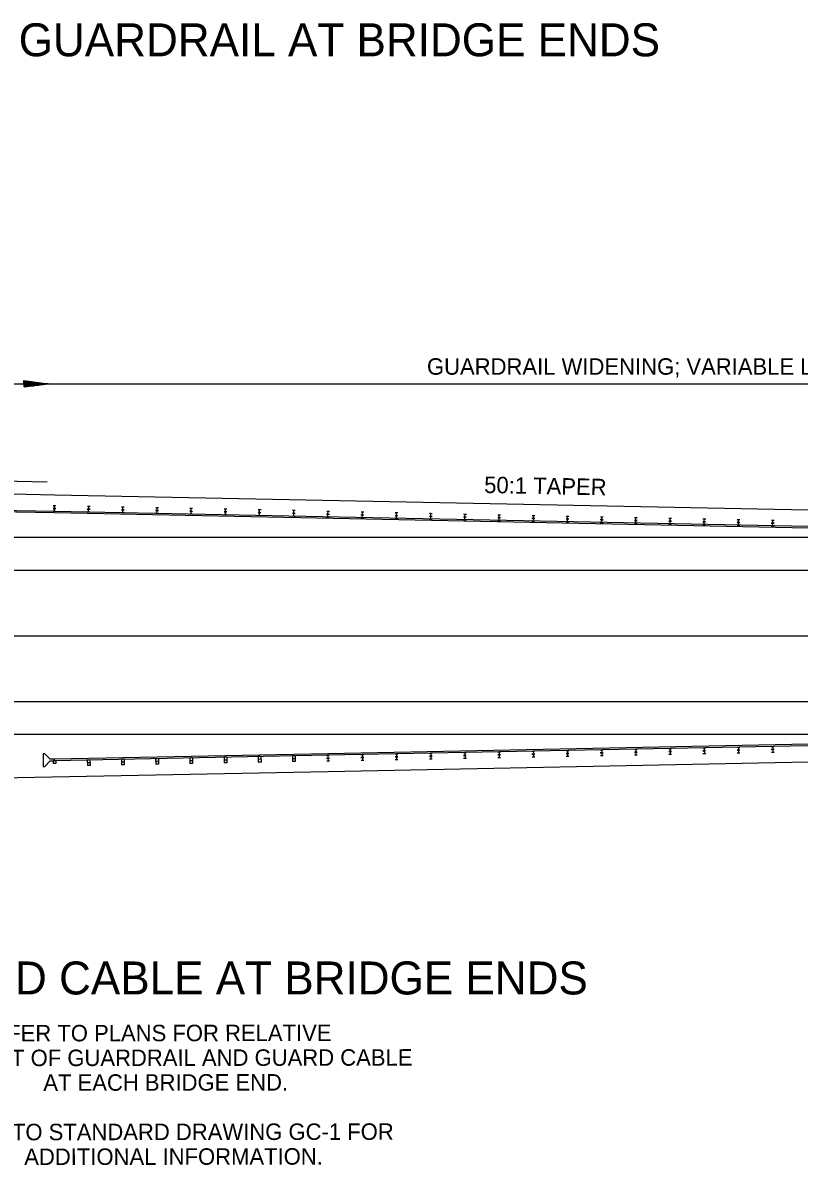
# Model space of a CAD drawing. Extents: x -2842 to 2681, y -2139 to 474.
# Drawn here: x -2274.9 to -1992.1, y -1829.5 to -1413.5 of the extents above; entities that cross this region are included whole.
import ezdxf

# ---------------------------------------------------------------- set-up
doc = ezdxf.new("R2010")
doc.units = 0
for name, color, linetype in [('Default', 7, 'Continuous'), ('R_Border', 7, 'Continuous'), ('R_Border Notes', 7, 'Continuous'), ('R_Grid', 7, 'Continuous')]:
    doc.layers.add(name, color=color, linetype=linetype)

msp = doc.modelspace()

# ---------------------------------------------------------------- linework, layer by layer
at = {"layer": 'Default'}
for p, q in [((-2263.31, -1585.48), (-2381.26, -1583.13)), ((-1814.89, -1594.45), (-2263.31, -1585.48)), ((-2263.45, -1592), (-2359.64, -1590.08)), ((-2263.43, -1591.46), (-2359.58, -1589.54)), ((-2263.43, -1591.46), (-2263.93, -1591.46)), ((-2263.41, -1590.39), (-2263.91, -1590.37)), ((-2263.41, -1590.47), (-2263.91, -1590.47)), ((-2263.39, -1589.39), (-2263.89, -1589.37)), ((-1815.02, -1600.97), (-2263.45, -1592)), ((-2263.43, -1591.46), (-2263.41, -1590.47)), ((-1815, -1600.43), (-2263.43, -1591.46)), ((-2262.93, -1591.48), (-2263.43, -1591.46)), ((-2263.41, -1590.39), (-2263.39, -1589.39)), ((-2262.91, -1590.41), (-2263.41, -1590.39)), ((-2262.91, -1590.49), (-2263.41, -1590.47)), ((-2262.89, -1589.41), (-2263.39, -1589.39)), ((-2250.97, -1591.72), (-2251.49, -1591.7)), ((-2250.95, -1590.65), (-2251.45, -1590.63)), ((-2250.97, -1590.72), (-2251.45, -1590.7)), ((-2250.93, -1589.65), (-2251.43, -1589.63)), ((-2250.97, -1591.72), (-2250.97, -1590.72)), ((-2250.46, -1590.72), (-2250.97, -1590.72)), ((-2250.5, -1591.72), (-2250.97, -1591.72)), ((-2250.95, -1590.65), (-2250.93, -1589.65)), ((-2250.46, -1590.65), (-2250.95, -1590.65)), ((-2250.44, -1589.65), (-2250.93, -1589.65)), ((-2238.54, -1591.96), (-2239.04, -1591.96)), ((-2238.5, -1590.88), (-2239.02, -1590.88)), ((-2238.52, -1590.96), (-2239.02, -1590.96)), ((-2238.5, -1589.89), (-2238.98, -1589.89)), ((-2238.54, -1591.96), (-2238.52, -1590.96)), ((-2238.04, -1591.98), (-2238.54, -1591.96)), ((-2238.02, -1590.98), (-2238.52, -1590.96)), ((-2238.5, -1590.88), (-2238.5, -1589.89)), ((-2237.98, -1589.89), (-2238.5, -1589.89)), ((-2238.02, -1590.88), (-2238.5, -1590.88)), ((-2226.08, -1592.22), (-2226.58, -1592.2)), ((-2226.06, -1591.12), (-2226.56, -1591.12)), ((-2226.06, -1591.22), (-2226.56, -1591.2)), ((-2226.04, -1590.13), (-2226.54, -1590.13)), ((-2226.08, -1592.22), (-2226.06, -1591.22)), ((-2225.58, -1592.22), (-2226.08, -1592.22)), ((-2226.06, -1591.12), (-2226.04, -1590.13)), ((-2225.56, -1591.14), (-2226.06, -1591.12)), ((-2225.56, -1591.22), (-2226.06, -1591.22)), ((-2225.54, -1590.15), (-2226.04, -1590.13)), ((-2213.62, -1592.46), (-2214.12, -1592.46)), ((-2213.6, -1591.38), (-2214.1, -1591.38)), ((-2213.6, -1591.46), (-2214.1, -1591.46)), ((-2213.58, -1590.39), (-2214.08, -1590.39)), ((-2213.62, -1592.46), (-2213.6, -1591.46)), ((-2213.12, -1592.48), (-2213.62, -1592.46)), ((-2213.6, -1591.38), (-2213.58, -1590.39)), ((-2213.1, -1591.4), (-2213.6, -1591.38)), ((-2213.1, -1591.48), (-2213.6, -1591.46)), ((-2213.08, -1590.41), (-2213.58, -1590.39)), ((-2201.17, -1592.72), (-2201.66, -1592.7)), ((-2201.15, -1591.64), (-2201.64, -1591.62)), ((-2201.15, -1591.72), (-2201.64, -1591.7)), ((-2201.13, -1590.65), (-2201.62, -1590.63)), ((-2201.17, -1592.72), (-2201.15, -1591.72)), ((-2200.67, -1592.72), (-2201.17, -1592.72)), ((-2201.15, -1591.64), (-2201.13, -1590.65)), ((-2200.65, -1591.64), (-2201.15, -1591.64)), ((-2200.65, -1591.72), (-2201.15, -1591.72)), ((-2200.63, -1590.65), (-2201.13, -1590.65)), ((-2188.71, -1592.96), (-2189.21, -1592.96)), ((-2188.69, -1591.88), (-2189.19, -1591.88)), ((-2188.69, -1591.96), (-2189.19, -1591.96)), ((-2188.67, -1590.88), (-2189.17, -1590.88)), ((-2188.71, -1592.96), (-2188.69, -1591.96)), ((-2188.21, -1592.98), (-2188.71, -1592.96)), ((-2188.69, -1591.88), (-2188.67, -1590.88)), ((-2188.19, -1591.9), (-2188.69, -1591.88)), ((-2188.19, -1591.98), (-2188.69, -1591.96)), ((-2188.17, -1590.9), (-2188.67, -1590.88)), ((-2176.25, -1593.22), (-2176.75, -1593.2)), ((-2176.23, -1592.14), (-2176.73, -1592.12)), ((-2176.23, -1592.22), (-2176.73, -1592.2)), ((-2176.21, -1591.14), (-2176.71, -1591.12)), ((-2176.25, -1593.22), (-2176.23, -1592.22)), ((-2175.75, -1593.22), (-2176.25, -1593.22)), ((-2176.23, -1592.14), (-2176.21, -1591.14)), ((-2175.73, -1592.14), (-2176.23, -1592.14)), ((-2175.73, -1592.22), (-2176.23, -1592.22)), ((-2175.71, -1591.14), (-2176.21, -1591.14)), ((-2164.27, -1592.36), (-2163.78, -1592.38)), ((-2164.27, -1592.44), (-2163.78, -1592.46)), ((-2164.25, -1591.36), (-2163.76, -1591.38)), ((-2163.8, -1593.46), (-2163.78, -1592.46)), ((-2163.78, -1592.38), (-2163.76, -1591.38)), ((-2163.78, -1592.38), (-2163.28, -1592.38)), ((-2163.78, -1592.46), (-2163.28, -1592.46)), ((-2163.76, -1591.38), (-2163.26, -1591.38)), ((-2151.76, -1592.62), (-2151.26, -1592.62)), ((-2151.76, -1592.7), (-2151.26, -1592.7)), ((-2151.74, -1591.62), (-2151.24, -1591.62)), ((-2151.28, -1593.69), (-2151.26, -1592.7)), ((-2151.26, -1592.62), (-2151.24, -1591.62)), ((-2151.26, -1592.62), (-2150.76, -1592.64)), ((-2151.26, -1592.7), (-2150.76, -1592.72)), ((-2151.24, -1591.62), (-2150.74, -1591.64)), ((-2139.3, -1592.86), (-2138.8, -1592.88)), ((-2139.3, -1592.94), (-2138.8, -1592.96)), ((-2139.28, -1591.86), (-2138.78, -1591.88)), ((-2138.82, -1593.95), (-2138.8, -1592.96)), ((-2138.8, -1592.88), (-2138.78, -1591.88)), ((-2138.8, -1592.88), (-2138.3, -1592.88)), ((-2138.8, -1592.96), (-2138.3, -1592.96)), ((-2138.78, -1591.88), (-2138.28, -1591.88)), ((-2126.84, -1593.12), (-2126.35, -1593.12)), ((-2126.84, -1593.2), (-2126.35, -1593.2)), ((-2126.82, -1592.12), (-2126.33, -1592.12)), ((-2126.37, -1594.19), (-2126.35, -1593.2)), ((-2126.35, -1593.12), (-2126.33, -1592.12)), ((-2126.35, -1593.12), (-2125.85, -1593.14)), ((-2126.35, -1593.2), (-2125.85, -1593.22)), ((-2126.33, -1592.12), (-2125.83, -1592.14)), ((-2114.37, -1592.36), (-2113.87, -1592.38)), ((-2113.89, -1593.38), (-2113.87, -1592.38)), ((-2113.87, -1592.38), (-2113.37, -1592.38)), ((-2101.91, -1592.62), (-2101.41, -1592.62)), ((-2101.43, -1593.61), (-2101.41, -1592.62)), ((-2101.41, -1592.62), (-2100.91, -1592.64)), ((-2089.45, -1592.86), (-2088.96, -1592.88)), ((-2088.98, -1593.87), (-2088.96, -1592.88)), ((-2088.96, -1592.88), (-2088.46, -1592.88)), ((-2077, -1593.12), (-2076.5, -1593.12)), ((-2076.52, -1594.11), (-2076.5, -1593.12)), ((-2076.5, -1593.12), (-2076, -1593.14)), ((-2164.29, -1593.44), (-2163.8, -1593.46)), ((-2163.8, -1593.46), (-2163.3, -1593.46)), ((-2151.78, -1593.69), (-2151.28, -1593.69)), ((-2151.28, -1593.69), (-2150.78, -1593.71)), ((-2139.32, -1593.93), (-2138.82, -1593.95)), ((-2138.82, -1593.95), (-2138.32, -1593.95)), ((-2126.86, -1594.19), (-2126.37, -1594.19)), ((-2126.37, -1594.19), (-2125.87, -1594.21)), ((-2114.41, -1594.43), (-2113.91, -1594.45)), ((-2114.39, -1593.36), (-2113.89, -1593.38)), ((-2114.39, -1593.44), (-2113.89, -1593.46)), ((-2113.91, -1594.45), (-2113.89, -1593.46)), ((-2113.91, -1594.45), (-2113.41, -1594.45)), ((-2113.89, -1593.38), (-2113.39, -1593.38)), ((-2113.89, -1593.46), (-2113.39, -1593.46)), ((-2101.95, -1594.69), (-2101.45, -1594.69)), ((-2101.93, -1593.61), (-2101.43, -1593.61)), ((-2101.93, -1593.69), (-2101.43, -1593.69)), ((-2101.45, -1594.69), (-2101.43, -1593.69)), ((-2101.45, -1594.69), (-2100.95, -1594.71)), ((-2101.43, -1593.61), (-2100.93, -1593.63)), ((-2101.43, -1593.69), (-2100.93, -1593.71)), ((-2089.49, -1594.93), (-2089, -1594.95)), ((-2089.47, -1593.85), (-2088.98, -1593.87)), ((-2089.47, -1593.93), (-2088.98, -1593.95)), ((-2089, -1594.95), (-2088.98, -1593.95)), ((-2089, -1594.95), (-2088.5, -1594.95)), ((-2088.98, -1593.87), (-2088.48, -1593.87)), ((-2088.98, -1593.95), (-2088.48, -1593.95)), ((-2077.06, -1595.19), (-2076.54, -1595.19)), ((-2077.02, -1594.11), (-2076.52, -1594.11)), ((-2077.02, -1594.19), (-2076.54, -1594.19)), ((-2076.54, -1595.19), (-2076.54, -1594.19)), ((-2076.54, -1594.19), (-2076.02, -1594.21)), ((-2076.54, -1595.19), (-2076.06, -1595.21)), ((-2076.52, -1594.11), (-2076.02, -1594.13)), ((-2064.6, -1595.43), (-2064.1, -1595.45)), ((-2064.58, -1594.35), (-2064.06, -1594.37)), ((-2064.58, -1594.43), (-2064.08, -1594.45)), ((-2064.54, -1593.36), (-2064.06, -1593.38)), ((-2064.1, -1595.45), (-2064.08, -1594.45)), ((-2064.1, -1595.45), (-2063.6, -1595.45)), ((-2064.08, -1594.45), (-2063.58, -1594.45)), ((-2064.06, -1594.37), (-2064.06, -1593.38)), ((-2064.06, -1593.38), (-2063.54, -1593.38)), ((-2064.06, -1594.37), (-2063.58, -1594.37)), ((-2052.14, -1595.69), (-2051.64, -1595.69)), ((-2052.12, -1594.61), (-2051.62, -1594.61)), ((-2052.12, -1594.69), (-2051.62, -1594.69)), ((-2052.1, -1593.61), (-2051.6, -1593.61)), ((-2051.64, -1595.69), (-2051.62, -1594.69)), ((-2051.64, -1595.69), (-2051.15, -1595.71)), ((-2051.62, -1594.61), (-2051.6, -1593.61)), ((-2051.62, -1594.61), (-2051.13, -1594.63)), ((-2051.62, -1594.69), (-2051.13, -1594.71)), ((-2051.6, -1593.61), (-2051.11, -1593.63)), ((-2039.69, -1595.93), (-2039.19, -1595.95)), ((-2039.67, -1594.85), (-2039.17, -1594.87)), ((-2039.67, -1594.93), (-2039.17, -1594.95)), ((-2039.65, -1593.85), (-2039.15, -1593.87)), ((-2039.19, -1595.95), (-2039.17, -1594.95)), ((-2039.19, -1595.95), (-2038.69, -1595.95)), ((-2039.17, -1594.87), (-2039.15, -1593.87)), ((-2039.17, -1594.87), (-2038.67, -1594.87)), ((-2039.17, -1594.95), (-2038.67, -1594.95)), ((-2039.15, -1593.87), (-2038.65, -1593.87)), ((-2027.23, -1596.19), (-2026.73, -1596.19)), ((-2027.21, -1595.11), (-2026.71, -1595.11)), ((-2027.21, -1595.19), (-2026.71, -1595.19)), ((-2027.19, -1594.11), (-2026.69, -1594.11)), ((-2026.73, -1596.19), (-2026.71, -1595.19)), ((-2026.73, -1596.19), (-2026.23, -1596.21)), ((-2026.71, -1595.11), (-2026.69, -1594.11)), ((-2026.71, -1595.11), (-2026.21, -1595.13)), ((-2026.71, -1595.19), (-2026.21, -1595.21)), ((-2026.69, -1594.11), (-2026.19, -1594.13)), ((-2014.77, -1596.43), (-2014.27, -1596.44)), ((-2014.75, -1595.35), (-2014.25, -1595.37)), ((-2014.75, -1595.43), (-2014.25, -1595.45)), ((-2014.73, -1594.35), (-2014.23, -1594.37)), ((-2014.27, -1596.44), (-2014.25, -1595.45)), ((-2014.27, -1596.44), (-2013.78, -1596.44)), ((-2014.25, -1595.37), (-2014.23, -1594.37)), ((-2014.25, -1595.37), (-2013.76, -1595.37)), ((-2014.25, -1595.45), (-2013.76, -1595.45)), ((-2014.23, -1594.37), (-2013.74, -1594.37)), ((-2002.32, -1596.68), (-2001.82, -1596.68)), ((-2002.3, -1595.61), (-2001.8, -1595.61)), ((-2002.3, -1595.69), (-2001.8, -1595.69)), ((-2002.28, -1594.61), (-2001.78, -1594.61)), ((-2001.82, -1596.68), (-2001.8, -1595.69)), ((-2001.82, -1596.68), (-2001.32, -1596.7)), ((-2001.8, -1595.61), (-2001.78, -1594.61)), ((-2001.8, -1595.61), (-2001.3, -1595.63)), ((-2001.8, -1595.69), (-2001.3, -1595.71)), ((-2001.78, -1594.61), (-2001.28, -1594.63)), ((-1815.02, -1600.97), (-2381.26, -1600.97)), ((-1662.85, -1612.93), (-2773.74, -1612.93)), ((-1661.2, -1660.76), (-2773.74, -1660.76)), ((-1815.02, -1672.72), (-2773.74, -1672.72)), ((-1815.02, -1672.72), (-2163.82, -1679.7)), ((-1815, -1673.26), (-2163.8, -1680.23)), ((-2163.82, -1679.7), (-2263.45, -1681.67)), ((-2163.8, -1680.23), (-2263.43, -1682.21)), ((-2176.25, -1680.47), (-2176.75, -1680.49)), ((-2176.75, -1680.49), (-2176.71, -1682.49)), ((-2175.75, -1680.47), (-2176.25, -1680.47)), ((-2175.75, -1680.47), (-2175.71, -1682.47)), ((-2164.29, -1680.23), (-2163.8, -1680.23)), ((-2163.8, -1680.23), (-2163.3, -1680.21)), ((-2163.8, -1680.23), (-2163.78, -1681.23)), ((-1814.89, -1679.24), (-2163.68, -1686.21)), ((-2151.78, -1679.98), (-2151.28, -1679.98)), ((-2151.28, -1679.98), (-2150.78, -1679.98)), ((-2151.28, -1679.98), (-2151.26, -1680.97)), ((-2139.32, -1679.74), (-2138.82, -1679.74)), ((-2138.82, -1679.74), (-2138.32, -1679.72)), ((-2138.82, -1679.74), (-2138.8, -1680.73)), ((-2126.86, -1679.5), (-2126.37, -1679.48)), ((-2126.84, -1680.49), (-2126.35, -1680.47)), ((-2126.84, -1680.57), (-2126.35, -1680.55)), ((-2126.37, -1679.48), (-2125.87, -1679.46)), ((-2126.37, -1679.48), (-2126.35, -1680.47)), ((-2126.35, -1680.47), (-2125.85, -1680.45)), ((-2126.35, -1680.55), (-2125.85, -1680.55)), ((-2126.35, -1680.55), (-2126.33, -1681.55)), ((-2114.41, -1679.24), (-2113.91, -1679.22)), ((-2114.39, -1680.23), (-2113.89, -1680.21)), ((-2114.39, -1680.31), (-2113.89, -1680.31)), ((-2113.91, -1679.22), (-2113.41, -1679.22)), ((-2113.91, -1679.22), (-2113.89, -1680.21)), ((-2113.89, -1680.21), (-2113.39, -1680.21)), ((-2113.89, -1680.31), (-2113.39, -1680.29)), ((-2113.89, -1680.31), (-2113.87, -1681.31)), ((-2101.95, -1679), (-2101.45, -1678.98)), ((-2101.93, -1680), (-2101.43, -1679.98)), ((-2101.93, -1680.08), (-2101.43, -1680.06)), ((-2101.45, -1678.98), (-2100.95, -1678.98)), ((-2101.45, -1678.98), (-2101.43, -1679.98)), ((-2101.43, -1679.98), (-2100.93, -1679.98)), ((-2101.43, -1680.06), (-2100.93, -1680.06)), ((-2101.43, -1680.06), (-2101.41, -1681.05)), ((-2089.49, -1678.74), (-2089, -1678.74)), ((-2089.47, -1679.74), (-2088.98, -1679.74)), ((-2089.47, -1679.82), (-2088.98, -1679.82)), ((-2089, -1678.74), (-2088.5, -1678.72)), ((-2089, -1678.74), (-2088.98, -1679.74)), ((-2088.98, -1679.74), (-2088.48, -1679.72)), ((-2088.98, -1679.82), (-2088.48, -1679.8)), ((-2088.98, -1679.82), (-2088.96, -1680.81)), ((-2077.06, -1678.5), (-2076.54, -1678.48)), ((-2077.02, -1679.5), (-2076.54, -1679.48)), ((-2077.02, -1679.58), (-2076.52, -1679.56)), ((-2077, -1680.57), (-2076.5, -1680.55)), ((-2076.54, -1678.48), (-2076.06, -1678.48)), ((-2076.54, -1678.48), (-2076.54, -1679.48)), ((-2076.54, -1679.48), (-2076.02, -1679.48)), ((-2076.52, -1679.56), (-2076.02, -1679.56)), ((-2076.52, -1679.56), (-2076.5, -1680.55)), ((-2076.5, -1680.55), (-2076, -1680.55)), ((-2064.6, -1678.24), (-2064.1, -1678.24)), ((-2064.58, -1679.24), (-2064.08, -1679.24)), ((-2064.58, -1679.32), (-2064.06, -1679.32)), ((-2064.54, -1680.31), (-2064.06, -1680.31)), ((-2064.1, -1678.24), (-2063.6, -1678.22)), ((-2064.1, -1678.24), (-2064.08, -1679.24)), ((-2064.08, -1679.24), (-2063.58, -1679.22)), ((-2064.06, -1679.32), (-2063.58, -1679.3)), ((-2064.06, -1679.32), (-2064.06, -1680.31)), ((-2064.06, -1680.31), (-2063.54, -1680.29)), ((-2052.14, -1678), (-2051.64, -1677.98)), ((-2052.12, -1679), (-2051.62, -1678.98)), ((-2052.12, -1679.08), (-2051.62, -1679.06)), ((-2052.1, -1680.08), (-2051.6, -1680.06)), ((-2051.64, -1677.98), (-2051.15, -1677.98)), ((-2051.64, -1677.98), (-2051.62, -1678.98)), ((-2051.62, -1678.98), (-2051.13, -1678.98)), ((-2051.62, -1679.06), (-2051.13, -1679.06)), ((-2051.62, -1679.06), (-2051.6, -1680.06)), ((-2051.6, -1680.06), (-2051.11, -1680.06)), ((-2039.69, -1677.74), (-2039.19, -1677.74)), ((-2039.67, -1678.74), (-2039.17, -1678.74)), ((-2039.67, -1678.82), (-2039.17, -1678.82)), ((-2039.65, -1679.82), (-2039.15, -1679.82)), ((-2039.19, -1677.74), (-2038.69, -1677.72)), ((-2039.19, -1677.74), (-2039.17, -1678.74)), ((-2039.17, -1678.74), (-2038.67, -1678.72)), ((-2039.17, -1678.82), (-2038.67, -1678.8)), ((-2039.17, -1678.82), (-2039.15, -1679.82)), ((-2039.15, -1679.82), (-2038.65, -1679.8)), ((-2027.23, -1677.5), (-2026.73, -1677.48)), ((-2027.21, -1678.5), (-2026.71, -1678.48)), ((-2027.21, -1678.58), (-2026.71, -1678.56)), ((-2027.19, -1679.58), (-2026.69, -1679.56)), ((-2026.73, -1677.48), (-2026.23, -1677.48)), ((-2026.73, -1677.48), (-2026.71, -1678.48)), ((-2026.71, -1678.48), (-2026.21, -1678.48)), ((-2026.71, -1678.56), (-2026.21, -1678.56)), ((-2026.71, -1678.56), (-2026.69, -1679.56)), ((-2026.69, -1679.56), (-2026.19, -1679.56)), ((-2014.77, -1677.24), (-2014.27, -1677.24)), ((-2014.75, -1678.24), (-2014.25, -1678.24)), ((-2014.75, -1678.32), (-2014.25, -1678.32)), ((-2014.73, -1679.32), (-2014.23, -1679.32)), ((-2014.27, -1677.24), (-2013.78, -1677.22)), ((-2014.27, -1677.24), (-2014.25, -1678.24)), ((-2014.25, -1678.24), (-2013.76, -1678.22)), ((-2014.25, -1678.32), (-2013.76, -1678.3)), ((-2014.25, -1678.32), (-2014.23, -1679.32)), ((-2014.23, -1679.32), (-2013.74, -1679.3)), ((-2002.32, -1677.01), (-2001.82, -1676.99)), ((-2002.3, -1678), (-2001.8, -1677.98)), ((-2002.3, -1678.08), (-2001.8, -1678.06)), ((-2002.28, -1679.08), (-2001.78, -1679.06)), ((-2001.82, -1676.99), (-2001.32, -1676.99)), ((-2001.82, -1676.99), (-2001.8, -1677.98)), ((-2001.8, -1677.98), (-2001.3, -1677.98)), ((-2001.8, -1678.06), (-2001.3, -1678.06)), ((-2001.8, -1678.06), (-2001.78, -1679.06)), ((-2001.78, -1679.06), (-2001.28, -1679.06)), ((-2263.43, -1682.21), (-2263.93, -1682.23)), ((-2263.93, -1682.23), (-2263.91, -1683.22)), ((-2262.91, -1683.2), (-2263.91, -1683.22)), ((-2263.43, -1682.21), (-2263.45, -1681.67)), ((-2262.93, -1682.21), (-2263.43, -1682.21)), ((-2262.93, -1682.21), (-2262.91, -1683.2)), ((-2251.47, -1681.97), (-2251.43, -1683.96)), ((-2250.97, -1681.97), (-2251.47, -1681.97)), ((-2250.46, -1682.95), (-2251.45, -1682.97)), ((-2250.44, -1683.94), (-2251.43, -1683.96)), ((-2250.48, -1681.95), (-2250.97, -1681.97)), ((-2250.48, -1681.95), (-2250.44, -1683.94)), ((-2238.52, -1681.71), (-2239.02, -1681.73)), ((-2239.02, -1681.73), (-2238.98, -1683.72)), ((-2238, -1682.71), (-2239, -1682.73)), ((-2237.98, -1683.7), (-2238.98, -1683.72)), ((-2238.02, -1681.71), (-2238.52, -1681.71)), ((-2238.02, -1681.71), (-2237.98, -1683.7)), ((-2226.58, -1681.47), (-2226.54, -1683.46)), ((-2226.06, -1681.47), (-2226.58, -1681.47)), ((-2225.54, -1682.45), (-2226.54, -1682.47)), ((-2225.54, -1683.44), (-2226.54, -1683.46)), ((-2225.58, -1681.45), (-2226.06, -1681.47)), ((-2225.58, -1681.45), (-2225.54, -1683.44)), ((-2213.62, -1681.21), (-2214.12, -1681.23)), ((-2214.12, -1681.23), (-2214.08, -1683.22)), ((-2213.1, -1682.21), (-2214.1, -1682.23)), ((-2213.08, -1683.2), (-2214.08, -1683.22)), ((-2213.12, -1681.21), (-2213.62, -1681.21)), ((-2213.12, -1681.21), (-2213.08, -1683.2)), ((-2201.66, -1680.97), (-2201.62, -1682.97)), ((-2201.17, -1680.97), (-2201.66, -1680.97)), ((-2200.65, -1681.97), (-2201.64, -1681.97)), ((-2200.63, -1682.97), (-2201.62, -1682.97)), ((-2200.67, -1680.97), (-2201.17, -1680.97)), ((-2200.67, -1680.97), (-2200.63, -1682.97)), ((-2189.21, -1680.73), (-2189.17, -1682.73)), ((-2188.71, -1680.73), (-2189.21, -1680.73)), ((-2188.19, -1681.71), (-2189.19, -1681.73)), ((-2188.17, -1682.71), (-2189.17, -1682.73)), ((-2188.21, -1680.71), (-2188.71, -1680.73)), ((-2188.21, -1680.71), (-2188.17, -1682.71)), ((-2175.73, -1681.47), (-2176.73, -1681.49)), ((-2175.71, -1682.47), (-2176.71, -1682.49)), ((-2164.27, -1681.23), (-2163.78, -1681.23)), ((-2164.27, -1681.31), (-2163.78, -1681.31)), ((-2164.25, -1682.31), (-2163.76, -1682.31)), ((-2163.78, -1681.23), (-2163.28, -1681.21)), ((-2163.78, -1681.31), (-2163.28, -1681.29)), ((-2163.78, -1681.31), (-2163.76, -1682.31)), ((-2163.76, -1682.31), (-2163.26, -1682.29)), ((-2151.76, -1680.97), (-2151.26, -1680.97)), ((-2151.76, -1681.07), (-2151.26, -1681.05)), ((-2151.74, -1682.07), (-2151.24, -1682.05)), ((-2151.26, -1680.97), (-2150.76, -1680.97)), ((-2151.26, -1681.05), (-2150.76, -1681.05)), ((-2151.26, -1681.05), (-2151.24, -1682.05)), ((-2151.24, -1682.05), (-2150.74, -1682.05)), ((-2139.3, -1680.73), (-2138.8, -1680.73)), ((-2139.3, -1680.81), (-2138.8, -1680.81)), ((-2139.28, -1681.81), (-2138.78, -1681.81)), ((-2138.8, -1680.73), (-2138.3, -1680.71)), ((-2138.8, -1680.81), (-2138.3, -1680.79)), ((-2138.8, -1680.81), (-2138.78, -1681.81)), ((-2138.78, -1681.81), (-2138.28, -1681.79)), ((-2126.82, -1681.57), (-2126.33, -1681.55)), ((-2126.33, -1681.55), (-2125.83, -1681.55)), ((-2114.37, -1681.31), (-2113.87, -1681.31)), ((-2113.87, -1681.31), (-2113.37, -1681.29)), ((-2101.91, -1681.07), (-2101.41, -1681.05)), ((-2101.41, -1681.05), (-2100.91, -1681.05)), ((-2089.45, -1680.81), (-2088.96, -1680.81)), ((-2088.96, -1680.81), (-2088.46, -1680.79)), ((-2163.68, -1686.21), (-2283.36, -1688.59))]:
    msp.add_line(p, q, dxfattribs=at)
msp.add_lwpolyline([(-2500.66, -1577.94), (-2380.62, -1578.11), (-2266.04, -1580.67)], dxfattribs=at)
msp.add_lwpolyline([(-2264.93, -1682.25), (-2263.43, -1682.21), (-2263.45, -1681.67), (-2264.95, -1681.71), (-2266.9, -1679.68), (-2267.56, -1679.68), (-2267.54, -1684.28), (-2266.88, -1684.28)], close=True, dxfattribs=at)
at = {"layer": 'R_Border Notes'}
for p, q in [((-2363.24, -1544.95), (-1716.57, -1544.95)), ((-2274.52, -1543.81), (-2265.69, -1544.95)), ((-2274.51, -1546.1), (-2274.52, -1543.81)), ((-2274.52, -1544.03), (-2272.79, -1544.03)), ((-2274.52, -1544.27), (-2271, -1544.26)), ((-2274.52, -1544.49), (-2269.22, -1544.5)), ((-2274.52, -1544.73), (-2267.49, -1544.73)), ((-2265.69, -1544.95), (-2274.52, -1544.95)), ((-2274.52, -1545.41), (-2269.21, -1545.4)), ((-2274.52, -1545.87), (-2272.78, -1545.86)), ((-2274.51, -1546.1), (-2265.69, -1544.95)), ((-2274.51, -1545.18), (-2267.48, -1545.18)), ((-2274.51, -1545.64), (-2271, -1545.64))]:
    msp.add_line(p, q, dxfattribs=at)
at = {"layer": 'R_Grid'}
msp.add_line((-1662.85, -1636.84), (-2773.74, -1636.84), dxfattribs=at)

# ---------------------------------------------------------------- texts
at = {"layer": 'R_Border'}
for s, height, rotation, p in [('TYPICAL LAYOUT OF GUARDRAIL AT BRIDGE ENDS', 12, 359.9999, (-2443.18, -1425.69)), ('50:1 TAPER', 6, 358.8601, (-2106.93, -1584.71)), ('DETAIL OF GUARD CABLE AT BRIDGE ENDS', 12, 359.9999, (-2411.53, -1767.33)), ('REFER TO PLANS FOR RELATIVE ', 6, 0.0775, (-2291.78, -1784.47)), ('PLACEMENT OF GUARDRAIL AND GUARD CABLE', 6, 0.0775, (-2323.37, -1793.51)), ('AT EACH BRIDGE END.', 6, 0.0775, (-2267.47, -1802.44)), ('REFER TO STANDARD DRAWING GC-1 FOR ', 6, 0.0775, (-2308.33, -1820.49)), ('ADDITIONAL INFORMATION.', 6, 0.0775, (-2274.42, -1829.45))]:
    msp.add_text(s, height=height, rotation=rotation, dxfattribs=at).set_placement(p)
msp.add_text('GUARDRAIL WIDENING; VARIABLE LENGTH', height=6, dxfattribs=at).set_placement((-2127.73, -1541.65))

doc.saveas('drawing.dxf')
